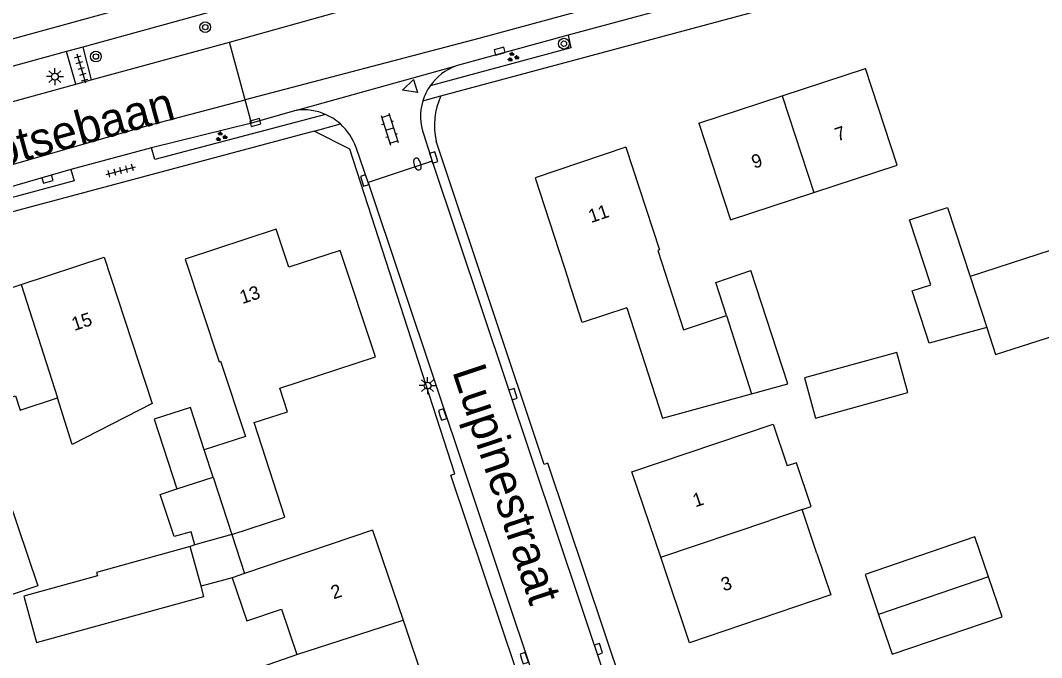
# Model space of a CAD drawing. Extents: x 136000 to 138005, y 398500 to 400500.
# Drawn here: x 137337.6 to 137413.3, y 398760.1 to 398807.3 of the extents above; entities that cross this region are included whole.
import ezdxf

# ---------------------------------------------------------------- set-up
doc = ezdxf.new("R2010")
doc.units = 0
for name, color, linetype in [('gg-anno-huisnummerreeks BGT', 7, 'Continuous'), ('gg-anno-openbare ruimte label', 7, 'Continuous'), ('gg-bbg-bijgebouw', 7, 'Continuous'), ('gg-bbg-gedigitaliseerde bebouwing', 7, 'Continuous'), ('gg-bbg-gedigitaliseerde bijgebouw', 7, 'Continuous'), ('gg-bbg-hoofdgebouw', 7, 'Continuous'), ('gg-bbg-luifel en loopbrug', 7, 'Continuous'), ('gg-bbg-tussenscheiding', 7, 'Continuous'), ('gg-knt-verharding', 7, 'Continuous'), ('gg-knt-verharding nz', 7, 'Continuous'), ('gt-grn-weggrens', 7, 'Continuous'), ('gt-symb-boom', 7, 'Continuous'), ('gt-symb-brandkraan', 7, 'Continuous'), ('gt-symb-groenvak', 7, 'Continuous'), ('gt-symb-klinker verharding', 7, 'Continuous'), ('gt-symb-kolk', 7, 'Continuous'), ('gt-symb-lichtmast', 7, 'Continuous'), ('gt-symb-tegel verharding', 7, 'Continuous'), ('gt-symb-waterafsluiter', 7, 'Continuous')]:
    doc.layers.add(name, color=color, linetype=linetype)

# ---------------------------------------------------------------- blocks, each defined once
blk = doc.blocks.new('gt0-GRVAK')
at = {"layer": 'gt-symb-groenvak'}
for p, q in [((-0.11, 0.189), (-0.228, 0.24)), ((-0.182, 0.153), (0.088, 0.153)), ((-0.091, 0.211), (-0.156, 0.322)), ((-0.047, 0.214), (-0.047, 0.393)), ((-0.004, 0.211), (0.061, 0.322)), ((0.015, 0.189), (0.133, 0.24)), ((0.262, -0.052), (0.197, 0.059)), ((0.305, -0.049), (0.305, 0.13)), ((0.349, -0.052), (0.414, 0.059)), ((-0.245, -0.228), (-0.363, -0.177)), ((-0.318, -0.264), (-0.047, -0.264)), ((-0.226, -0.206), (-0.291, -0.095)), ((-0.183, -0.203), (-0.183, -0.024)), ((-0.139, -0.206), (-0.074, -0.095)), ((-0.12, -0.228), (-0.002, -0.177)), ((0.243, -0.074), (0.125, -0.023)), ((0.17, -0.11), (0.441, -0.11)), ((0.368, -0.074), (0.486, -0.023))]:
    blk.add_line(p, q, dxfattribs=at)
blk = doc.blocks.new('gt0-KOLK')
at = {"layer": 'gt-symb-kolk'}
blk.add_lwpolyline([(0, 0), (0.375, 0), (0.375, 0.4), (-0.375, 0.4), (-0.375, 0), (0, 0)], dxfattribs=at)
blk = doc.blocks.new('gt0-BOOM')
at = {"layer": 'gt-symb-boom'}
for radius in [0.4, 0.2]:
    blk.add_circle((0, 0), radius, dxfattribs=at)
blk = doc.blocks.new('gt0-WAFSL')
at = {"layer": 'gt-symb-waterafsluiter'}
for p, q in [((-0.5, -0.333), (0, 0.667)), ((0, 0.667), (0.5, -0.333)), ((0.5, -0.333), (-0.5, -0.333))]:
    blk.add_line(p, q, dxfattribs=at)
blk = doc.blocks.new('gt0-LMAST')
at = {"layer": 'gt-symb-lichtmast'}
for p, q in [((-0.182, 0.173), (-0.447, 0.438)), ((-0.005, 0.246), (-0.005, 0.621)), ((0.172, 0.173), (0.437, 0.438)), ((-0.255, -0.004), (-0.63, -0.004)), ((-0.182, -0.181), (-0.447, -0.446)), ((-0.005, -0.254), (-0.005, -0.629)), ((0.437, -0.446), (0.172, -0.181)), ((0.245, -0.004), (0.62, -0.004))]:
    blk.add_line(p, q, dxfattribs=at)
blk.add_circle((-0.005, -0.004), 0.25, dxfattribs=at)
blk = doc.blocks.new('gt0-TEG1')
at = {"layer": 'gt-symb-tegel verharding'}
for p, q in [((-1.125, 0), (1.125, 0)), ((-0.9, -0.25), (-0.9, 0.25)), ((-0.45, -0.25), (-0.45, 0.25)), ((0, -0.25), (0, 0.25)), ((0.45, -0.25), (0.45, 0.25)), ((0.9, -0.25), (0.9, 0.25))]:
    blk.add_line(p, q, dxfattribs=at)
blk = doc.blocks.new('gt0-KL1')
at = {"layer": 'gt-symb-klinker verharding'}
for p, q in [((-1.15, 0.3), (1.15, 0.3)), ((-1, -0.3), (-1, 0.3)), ((-0.5, 0.3), (-0.5, 0.45)), ((0, -0.3), (0, 0.3)), ((0.5, 0.3), (0.5, 0.45)), ((1, -0.3), (1, 0.3)), ((-1.15, -0.3), (1.15, -0.3)), ((-0.5, -0.45), (-0.5, -0.3)), ((0.5, -0.45), (0.5, -0.3))]:
    blk.add_line(p, q, dxfattribs=at)
blk = doc.blocks.new('gt0-BR')
at = {"layer": 'gt-symb-brandkraan'}
for centre, radius, start, end in [((-0.244, 0), 0.206, 107.56694, 252.43307), ((0.599, -2.664), 3, 106.89205, 107.56694), ((0, -0.691), 0.938, 73.10799, 106.89205), ((-0.599, -2.664), 3, 72.43309, 73.10799), ((0.244, 0), 0.206, 287.56695, 72.43309), ((0.599, 2.664), 3, 252.43307, 253.10797), ((0, 0.691), 0.938, 253.10797, 286.89206), ((-0.599, 2.664), 3, 286.89206, 287.56695)]:
    blk.add_arc(centre, radius, start, end, dxfattribs=at)

msp = doc.modelspace()

# ---------------------------------------------------------------- linework, layer by layer
at = {"layer": 'gg-bbg-bijgebouw'}
msp.add_lwpolyline([(137351.239, 398775.524), (137350.219, 398778.658), (137347.526, 398777.779)], dxfattribs=at)
at = {"layer": 'gg-bbg-gedigitaliseerde bebouwing'}
for p, q in [((137351.9, 398773.497), (137353.286, 398769.244)), ((137396.631, 398767.841), (137395.556, 398771.084)), ((137363.72, 398769.55), (137354.232, 398766.34)), ((137354.232, 398766.34), (137353.305, 398766.027))]:
    msp.add_line(p, q, dxfattribs=at)
for points in [[(137396.414, 398794.589), (137402.584, 398796.614), (137400.23, 398803.78)], [(137387.89, 398799.73), (137390.244, 398792.564), (137396.414, 398794.589)], [(137391.793, 398779.671), (137394.482, 398780.411), (137391.748, 398788.812)], [(137331.49, 398785.73), (137333.891, 398778.42), (137337.252, 398779.525), (137337.604, 398778.455), (137340.358, 398779.36)], [(137382.55, 398786.03), (137385.209, 398777.859), (137391.793, 398779.671)], [(137353.286, 398769.244), (137357.216, 398770.524), (137354.932, 398777.531), (137357.402, 398778.336), (137356.83, 398780.09)], [(137347.378, 398778.936), (137341.463, 398775.916), (137340.358, 398779.36)], [(137382.93, 398773.89), (137393.404, 398777.425), (137394.447, 398774.329)], [(137395.556, 398771.084), (137396.211, 398771.303), (137395.132, 398774.556), (137394.447, 398774.329)], [(137396.631, 398767.841), (137397.671, 398764.755), (137387.2, 398761.22)], [(137353.305, 398766.027), (137354.385, 398762.839), (137356.964, 398763.713), (137358.108, 398760.336)], [(137357.625, 398753.351), (137355.623, 398752.658), (137353.515, 398758.745), (137358.108, 398760.336)]]:
    msp.add_lwpolyline(points, dxfattribs=at)
at = {"layer": 'gg-bbg-gedigitaliseerde bijgebouw'}
for p, q in [((137347.526, 398777.779), (137349.207, 398772.62)), ((137349.207, 398772.62), (137351.9, 398773.497)), ((137351.006, 398765.399), (137350.195, 398768.34))]:
    msp.add_line(p, q, dxfattribs=at)
for points in [[(137409.226, 398784.588), (137404.969, 398783.408), (137403.687, 398787.293), (137405.086, 398787.755), (137403.501, 398792.561), (137406.308, 398793.487), (137407.998, 398788.363)], [(137425.979, 398787.833), (137424.104, 398793.6), (137407.998, 398788.363)], [(137409.226, 398784.588), (137409.882, 398782.57), (137414.884, 398784.196)], [(137403.376, 398779.761), (137402.551, 398782.739), (137395.711, 398780.844), (137396.536, 398777.866), (137403.376, 398779.761)], [(137335.946, 398774.146), (137338.905, 398765.435), (137335.307, 398764.213), (137332.348, 398772.924), (137335.946, 398774.146)], [(137409.35, 398766.092), (137408.341, 398769.056), (137400.204, 398766.286), (137401.213, 398763.322)], [(137350.195, 398768.34), (137343.264, 398766.429), (137343.334, 398766.177), (137337.872, 398764.671), (137338.819, 398761.238), (137351.211, 398764.655), (137351.006, 398765.399)], [(137401.213, 398763.322), (137402.221, 398760.359), (137410.359, 398763.129), (137409.35, 398766.092)]]:
    msp.add_lwpolyline(points, dxfattribs=at)
at = {"layer": 'gg-bbg-hoofdgebouw'}
for p, q in [((137394.06, 398801.755), (137400.23, 398803.78)), ((137387.89, 398799.73), (137394.06, 398801.755)), ((137337.665, 398787.76), (137343.833, 398789.788)), ((137343.833, 398789.788), (137347.378, 398778.936)), ((137331.49, 398785.73), (137337.665, 398787.76)), ((137385.065, 398767.555), (137382.93, 398773.89)), ((137363.72, 398769.55), (137365.977, 398762.889)), ((137387.2, 398761.22), (137385.065, 398767.555)), ((137365.977, 398762.889), (137368.02, 398756.86))]:
    msp.add_line(p, q, dxfattribs=at)
for points in [[(137382.492, 398797.941), (137375.77, 398795.67), (137378.23, 398788.09)], [(137382.492, 398797.941), (137384.97, 398790.334), (137384.854, 398790.297), (137386.751, 398784.406), (137389.945, 398785.474)], [(137357.507, 398789.041), (137356.57, 398791.87), (137349.82, 398789.653)], [(137356.83, 398780.09), (137363.919, 398782.4), (137361.304, 398790.298), (137357.507, 398789.041)], [(137349.82, 398789.653), (137352.339, 398782.044), (137352.449, 398782.08), (137354.291, 398776.493), (137351.239, 398775.524)], [(137389.945, 398785.474), (137389.149, 398787.919), (137391.748, 398788.812)], [(137382.55, 398786.03), (137379.247, 398784.955), (137378.23, 398788.09)]]:
    msp.add_lwpolyline(points, dxfattribs=at)
at = {"layer": 'gg-bbg-luifel en loopbrug'}
for p, q in [((137353.286, 398769.244), (137350.536, 398768.471)), ((137353.286, 398769.244), (137354.232, 398766.34)), ((137350.536, 398768.471), (137350.195, 398768.34)), ((137353.305, 398766.027), (137351.006, 398765.399))]:
    msp.add_line(p, q, dxfattribs=at)
msp.add_lwpolyline([(137350.536, 398768.471), (137350.272, 398769.436), (137349.018, 398769.093), (137347.974, 398772.207), (137349.207, 398772.62)], dxfattribs=at)
at = {"layer": 'gg-bbg-tussenscheiding'}
for p, q in [((137394.06, 398801.755), (137396.414, 398794.589)), ((137337.665, 398787.76), (137340.358, 398779.36)), ((137407.998, 398788.363), (137409.226, 398784.588)), ((137389.945, 398785.474), (137391.793, 398779.671)), ((137351.9, 398773.497), (137351.239, 398775.524)), ((137395.556, 398771.084), (137393.152, 398770.281)), ((137385.065, 398767.555), (137393.152, 398770.281)), ((137409.35, 398766.092), (137401.213, 398763.322)), ((137358.108, 398760.336), (137365.977, 398762.889))]:
    msp.add_line(p, q, dxfattribs=at)
at = {"layer": 'gg-knt-verharding'}
for p, q in [((137368.78, 398801.749), (137436.25, 398819.89)), ((137366.23, 398813.982), (137322.569, 398802.008)), ((137361.926, 398810.799), (137342.238, 398805.359)), ((137389.997, 398809.438), (137378.206, 398806.242)), ((137353.116, 398805.737), (137362.573, 398808.38)), ((137378.206, 398806.242), (137369.896, 398803.964)), ((137342.238, 398805.359), (137341.022, 398805.025)), ((137342.238, 398805.359), (137342.868, 398802.937)), ((137342.868, 398802.937), (137353.116, 398805.737)), ((137354.274, 398801.454), (137353.116, 398805.737)), ((137341.022, 398805.025), (137322.273, 398799.891)), ((137341.732, 398802.626), (137341.022, 398805.025)), ((137341.732, 398802.626), (137342.868, 398802.937)), ((137354.745, 398799.714), (137354.274, 398801.454)), ((137358.106, 398800.695), (137354.745, 398799.714)), ((137354.745, 398799.714), (137347.327, 398797.899)), ((137367.504, 398798.852), (137368.12, 398796.902)), ((137347.327, 398797.899), (137341.351, 398796.282)), ((137363.388, 398795.319), (137362.487, 398797.917)), ((137368.12, 398796.902), (137363.388, 398795.319)), ((137368.12, 398796.902), (137388.509, 398736.035)), ((137363.388, 398795.319), (137382.776, 398737.347))]:
    msp.add_line(p, q, dxfattribs=at)
for points in [[(137378.206, 398806.242), (137378.403, 398805.312), (137367.986, 398802.498)], [(137328.692, 398799.02), (137333.18, 398800.28), (137341.732, 398802.626)], [(137360.232, 398800.374), (137347.576, 398797.029), (137347.327, 398797.899)], [(137359.39, 398799.13), (137329.63, 398791.17), (137316.12, 398786.05), (137315.961, 398786.441)], [(137411.82, 398649.129), (137403.74, 398672.78), (137401.59, 398672.03), (137379.59, 398736.49), (137381.73, 398737.19), (137369.51, 398773.64), (137369.82, 398773.74), (137362.03, 398797.8), (137359.39, 398799.13)], [(137418.3, 398651.269), (137410.19, 398675.1), (137411.69, 398678.35), (137391.4, 398737.81), (137389.27, 398737.03), (137376.71, 398774.53), (137376.43, 398774.43), (137368.43, 398798.39)], [(137341.351, 398796.282), (137341.595, 398795.45), (137331.605, 398792.765), (137331.482, 398793.303)], [(137341.351, 398796.282), (137333.15, 398793.91), (137331.482, 398793.303)]]:
    msp.add_lwpolyline(points, dxfattribs=at)
for centre, radius, start, end in [((137371.264, 398800.204), 4.001, 109.99659, 145.01872), ((137371.27, 398800.204), 4.006, 145.061, 162.99867), ((137371.259, 398800.211), 3.993, 163.05457, 199.897), ((137373.429, 398799.567), 5.136, 154.8564, 193.24636), ((137358.572, 398796.583), 4.139, 66.3586, 96.46919), ((137358.573, 398796.589), 4.132, 48.19983, 66.32443), ((137358.574, 398796.588), 4.132, 18.75827, 48.22876)]:
    msp.add_arc(centre, radius, start, end, dxfattribs=at)
at = {"layer": 'gg-knt-verharding nz'}
for points in [[(137392.819, 398811.79), (137371.591, 398806.005), (137354.274, 398801.454)], [(137301.761, 398780.103), (137304.227, 398781.942), (137307.739, 398784.112), (137318.029, 398789.738), (137322.103, 398791.66), (137326.699, 398793.453), (137333.724, 398795.713), (137347.165, 398799.586), (137354.274, 398801.454)]]:
    msp.add_lwpolyline(points, dxfattribs=at)
at = {"layer": 'gt-grn-weggrens'}
for p, q in [((137358.106, 398800.695), (137369.896, 398803.964)), ((137367.439, 398801.375), (137368.78, 398801.749)), ((137359.39, 398799.13), (137361.327, 398799.67))]:
    msp.add_line(p, q, dxfattribs=at)

# ---------------------------------------------------------------- block references
at = {"layer": 'gt-symb-boom'}
for p in [(137351.312, 398806.84), (137377.895, 398805.617), (137343.212, 398804.664)]:
    msp.add_blockref('gt0-BOOM', p, dxfattribs=at)
at = {"layer": 'gt-symb-brandkraan', "rotation": 107.81888891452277}
msp.add_blockref('gt0-BR', (137367.037, 398796.695), dxfattribs=at)
at = {"layer": 'gt-symb-groenvak'}
for p in [(137374.1, 398804.628), (137352.481, 398798.723)]:
    msp.add_blockref('gt0-GRVAK', p, dxfattribs=at)
at = {"layer": 'gt-symb-klinker verharding', "rotation": -72.48880443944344}
msp.add_blockref('gt0-KL1', (137364.984, 398799.29), dxfattribs=at)
at = {"layer": 'gt-symb-kolk'}
for p, rotation in [((137373.187, 398804.87), 15.300324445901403), ((137355.08, 398799.583), 15.134475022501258), ((137368.048, 398797.119), -72.59811208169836), ((137339.683, 398795.381), 16.07917237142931), ((137363.315, 398795.539), 108.36246843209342), ((137373.936, 398779.578), -71.51067367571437), ((137368.707, 398778.067), -71.51067367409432), ((137374.758, 398760.01), -71.51067367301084), ((137380.258, 398760.688), -71.51067367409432)]:
    msp.add_blockref('gt0-KOLK', p, dxfattribs=dict(at, rotation=rotation))
at = {"layer": 'gt-symb-lichtmast'}
for p in [(137340.18, 398803.176), (137367.794, 398780.275)]:
    msp.add_blockref('gt0-LMAST', p, dxfattribs=at)
at = {"layer": 'gt-symb-tegel verharding'}
for p, rotation in [((137342.128, 398803.788), -73.43253308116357), ((137345.054, 398796.202), 15.064233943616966)]:
    msp.add_blockref('gt0-TEG1', p, dxfattribs=dict(at, rotation=rotation))
at = {"layer": 'gt-symb-waterafsluiter', "rotation": 107.81888891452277}
msp.add_blockref('gt0-WAFSL', (137366.574, 398802.376), dxfattribs=at)

# ---------------------------------------------------------------- texts
at = {"layer": 'gg-anno-huisnummerreeks BGT'}
for s, rotation, p in [('7', 18.2, (137398.163, 398798.365)), ('9', 18.2, (137391.988, 398796.339)), ('11', 18.7, (137379.907, 398792.317)), ('13', 18.2, (137354.061, 398786.309)), ('15', 18.2, (137341.61, 398784.32)), ('1', 18.6, (137387.632, 398771.245)), ('3', 18.6, (137389.733, 398765.011)), ('2', 18.7, (137360.824, 398764.423))]:
    msp.add_text(s, height=1, rotation=rotation, dxfattribs=at).set_placement(p)
at = {"layer": 'gg-anno-openbare ruimte label'}
for s, rotation, p in [('Enschotsebaan', 15.4, (137327.008, 398793.935)), ('Lupinestraat', 288.4, (137369.598, 398781.337))]:
    msp.add_text(s, height=2.5, rotation=rotation, dxfattribs=at).set_placement(p)

doc.saveas('drawing.dxf')
